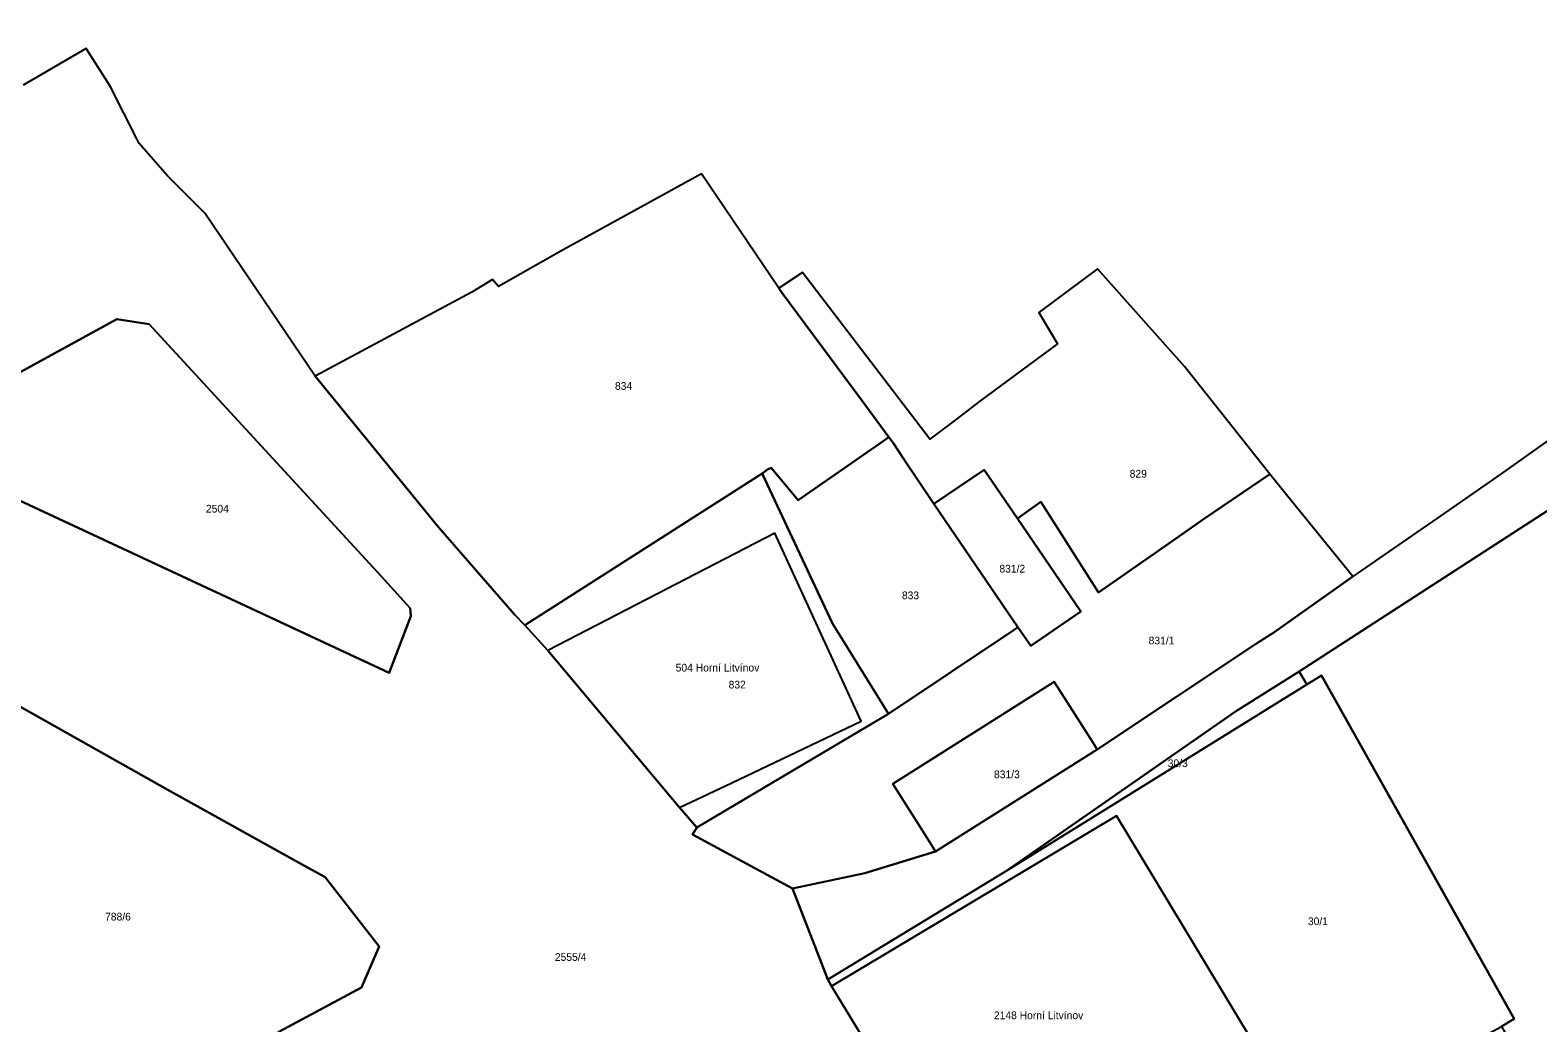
# Model space of a CAD drawing. Extents: x -792094 to -791524, y -979074 to -977761.
# Drawn here: x -791795.7 to -791698, y -978436.7 to -978372.3 of the extents above; entities that cross this region are included whole.
import ezdxf

# ---------------------------------------------------------------- set-up
doc = ezdxf.new("R2010")
doc.units = 0
doc.layers.add('katastr', color=7, linetype='Continuous')

msp = doc.modelspace()

# ---------------------------------------------------------------- linework, layer by layer
at = {"layer": 'katastr'}
for points in [[(-791639.24, -978372.34), (-791665.73, -978384.71), (-791679.28, -978391.82), (-791713.44, -978413.95), (-791712.96, -978414.79), (-791712, -978414.2), (-791699.5, -978436.46), (-791700.32, -978436.96), (-791699.69, -978438.07), (-791692.7, -978450.2), (-791683.8, -978465.99), (-791679.66, -978473.05), (-791670.22, -978489.33), (-791668.76, -978491.84), (-791668.28, -978492.67), (-791665.46, -978492.66), (-791655.51, -978492.64), (-791656.09, -978490.59), (-791634.23, -978485.99)], [(-791735.27, -978448.37), (-791743.77, -978434.34), (-791744.02, -978433.92), (-791746.31, -978428.01), (-791752.8, -978424.51), (-791752.51, -978424.06), (-791753.63, -978422.77), (-791762.18, -978412.57), (-791763.66, -978410.94), (-791764.34, -978410.24), (-791769.27, -978404.57), (-791777.27, -978394.78), (-791784.41, -978384.21), (-791786.85, -978381.8), (-791788.67, -978379.7), (-791788.82, -978379.4), (-791790.51, -978376.06), (-791790.72, -978375.73), (-791792.12, -978373.53), (-791796.2, -978375.9)], [(-791694.89, -978397.25), (-791700.34, -978401.11), (-791704.81, -978404.2), (-791705.84, -978404.92), (-791709.69, -978407.58), (-791709.96, -978407.77), (-791715.1, -978411.41), (-791716.21, -978412.13), (-791726.54, -978418.99), (-791737.03, -978425.61), (-791741.62, -978427.03), (-791746.31, -978428.01), (-791744.02, -978433.92), (-791732.42, -978426.87), (-791717.58, -978416.54), (-791713.44, -978413.95), (-791679.28, -978391.82)], [(-791796.41, -978416.2), (-791786.66, -978421.71), (-791778.16, -978426.44), (-791776.62, -978427.28), (-791773.12, -978431.78), (-791774.26, -978434.43), (-791779.62, -978437.31)]]:
    msp.add_lwpolyline(points, dxfattribs=at)
for points in [[(-791740.05, -978398.74), (-791741.86, -978396.29), (-791747.02, -978389.33), (-791747.2, -978389.07), (-791752.2, -978381.67), (-791761.17, -978386.59), (-791765.38, -978388.96), (-791765.76, -978388.52), (-791767.1, -978389.33), (-791777.27, -978394.78), (-791769.27, -978404.57), (-791764.34, -978410.24), (-791763.66, -978410.94), (-791748.28, -978401.09), (-791747.92, -978400.83), (-791747.69, -978400.72), (-791745.94, -978402.82), (-791740.65, -978399.16)], [(-791720.89, -978394.15), (-791725.1, -978389.42), (-791726.53, -978387.82), (-791730.33, -978390.65), (-791729.12, -978392.68), (-791734.15, -978396.41), (-791735.85, -978397.7), (-791737.4, -978398.87), (-791745.65, -978388.05), (-791747.2, -978389.07), (-791747.02, -978389.33), (-791741.86, -978396.29), (-791740.05, -978398.74), (-791739.78, -978399.1), (-791739.09, -978400.16), (-791737.13, -978403.07), (-791733.87, -978400.85), (-791731.71, -978404.01), (-791730.2, -978402.94), (-791726.47, -978408.81), (-791721.91, -978405.63), (-791719.59, -978404.02), (-791715.34, -978401.15)], [(-791772.98, -978407.76), (-791788.02, -978391.41), (-791790.13, -978391.09), (-791800.2, -978396.6), (-791801.06, -978397.22), (-791801.55, -978398.12), (-791801.66, -978399.13), (-791801.52, -978400.02), (-791800.96, -978400.74), (-791772.47, -978414.02), (-791771.06, -978410.36), (-791771.1, -978409.83)], [(-791771.1, -978409.83), (-791771.06, -978410.36), (-791772.47, -978414.02), (-791800.96, -978400.74), (-791801.52, -978400.02), (-791801.66, -978399.13), (-791801.55, -978398.12), (-791801.06, -978397.22), (-791800.2, -978396.6), (-791790.13, -978391.09), (-791788.02, -978391.41), (-791772.98, -978407.76)], [(-791748.28, -978401.09), (-791743.72, -978410.83), (-791740.09, -978416.68), (-791732, -978411.27), (-791731.69, -978411.06), (-791737.13, -978403.07), (-791739.09, -978400.16), (-791739.78, -978399.1), (-791740.05, -978398.74), (-791740.65, -978399.16), (-791745.94, -978402.82), (-791747.69, -978400.72), (-791747.92, -978400.83)], [(-791762.18, -978412.57), (-791753.63, -978422.77), (-791752.51, -978424.06), (-791740.09, -978416.68), (-791743.72, -978410.83), (-791748.28, -978401.09), (-791763.66, -978410.94)], [(-791726.54, -978418.99), (-791716.21, -978412.13), (-791715.1, -978411.41), (-791709.96, -978407.77), (-791710.24, -978407.43), (-791714.27, -978402.47), (-791715.34, -978401.15), (-791719.59, -978404.02), (-791721.91, -978405.63), (-791726.47, -978408.81), (-791730.2, -978402.94), (-791731.71, -978404.01), (-791727.6, -978410.05), (-791730.86, -978412.27), (-791731.69, -978411.06), (-791732, -978411.27), (-791740.09, -978416.68), (-791752.51, -978424.06), (-791752.8, -978424.51), (-791746.31, -978428.01), (-791741.62, -978427.03), (-791737.03, -978425.61), (-791737.49, -978424.89), (-791739.81, -978421.22), (-791729.33, -978414.62), (-791726.81, -978418.57)], [(-791733.87, -978400.85), (-791737.13, -978403.07), (-791731.69, -978411.06), (-791730.86, -978412.27), (-791727.6, -978410.05), (-791731.71, -978404.01)], [(-791731.71, -978404.01), (-791733.87, -978400.85), (-791737.13, -978403.07), (-791731.69, -978411.06), (-791730.86, -978412.27), (-791727.6, -978410.05)], [(-791750.25, -978421.16), (-791741.86, -978417.15), (-791747.46, -978404.97), (-791762.18, -978412.57), (-791753.63, -978422.77)], [(-791800.48, -978414.05), (-791800.29, -978417.39), (-791800.13, -978420.23), (-791799.16, -978437.14), (-791798.94, -978441.72), (-791798.74, -978445.45), (-791797.38, -978444.82), (-791795.52, -978444.13), (-791782.04, -978438.34), (-791779.62, -978437.31), (-791774.26, -978434.43), (-791773.12, -978431.78), (-791776.62, -978427.28), (-791778.16, -978426.44), (-791786.66, -978421.71), (-791796.41, -978416.2), (-791798.26, -978415.26)], [(-791731.58, -978454.53), (-791731.27, -978454.35), (-791707.49, -978440.91), (-791705.92, -978440.02), (-791704.52, -978439.23), (-791700.32, -978436.96), (-791699.5, -978436.46), (-791712, -978414.2), (-791712.96, -978414.79), (-791717.16, -978417.4), (-791732.42, -978426.87), (-791744.02, -978433.92), (-791743.77, -978434.34), (-791725.3, -978423.3), (-791715.73, -978439.15), (-791718.24, -978440.67), (-791717.65, -978441.64), (-791723.32, -978445.04), (-791723.9, -978444.08), (-791734.16, -978450.22), (-791733.91, -978450.62), (-791733.73, -978450.92)], [(-791717.16, -978417.4), (-791712.96, -978414.79), (-791713.44, -978413.95), (-791717.58, -978416.54), (-791732.42, -978426.87)], [(-791726.54, -978418.99), (-791726.81, -978418.57), (-791729.33, -978414.62), (-791739.81, -978421.22), (-791737.49, -978424.89), (-791737.03, -978425.61)], [(-791726.54, -978418.99), (-791726.81, -978418.57), (-791729.33, -978414.62), (-791739.81, -978421.22), (-791737.49, -978424.89), (-791737.03, -978425.61)], [(-791723.9, -978444.08), (-791718.24, -978440.67), (-791715.73, -978439.15), (-791725.3, -978423.3), (-791743.77, -978434.34), (-791735.27, -978448.37), (-791734.16, -978450.22)], [(-791715.73, -978439.15), (-791725.3, -978423.3), (-791743.77, -978434.34), (-791735.27, -978448.37), (-791734.16, -978450.22), (-791723.9, -978444.08), (-791723.32, -978445.04), (-791717.65, -978441.64), (-791718.24, -978440.67)]]:
    msp.add_lwpolyline(points, close=True, dxfattribs=at)

# ---------------------------------------------------------------- texts
for s, p in [('834', (-791757.82, -978395.67)), ('829', (-791724.44, -978401.36)), ('2504', (-791784.35, -978403.63)), ('831/2', (-791732.89, -978407.52)), ('833', (-791739.21, -978409.25)), ('831/1', (-791723.21, -978412.18)), ('504 Horní Litvínov', (-791753.885, -978413.94)), ('832', (-791750.45, -978415.04)), ('831/3', (-791733.24, -978420.86)), ('30/3', (-791721.97, -978420.14)), ('788/6', (-791790.89, -978430.09)), ('30/1', (-791712.88, -978430.39)), ('2555/4', (-791761.72, -978432.71)), ('2148 Horní Litvínov', (-791733.246, -978436.49))]:
    msp.add_text(s, height=0.5, dxfattribs=at).set_placement(p)

doc.saveas('drawing.dxf')
